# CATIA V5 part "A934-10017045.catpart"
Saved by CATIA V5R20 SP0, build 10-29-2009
Part number: A934-10017045
Source: Unknown
Property "A": "60.000"
Property "ARTICLENO": "A934-10017045"
Property "B": "20.000"
Property "BOMINFO": "A934-10017045"
Property "CODE": "A934-10017045"
Property "L": "170.000"
Property "L1": "143.370"
Property "LINA": "A934-10017045"
Property "NB": "A934-10017045"
Property "NBSYN": "$CODE."
Property "NN": "A934"
Property "NT": "VDI 3357 H-Type Cam Drivers, self-lubricating"
Property "SUPPLIER": "CF"
Property "T": "45.000"
Property "W": "100.000"
Bounding box of the stored display mesh (mm): x 0 to 170, y 0 to 45, z -100 to 0
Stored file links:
  C:\Users\Utente\Desktop\3D files A934\A934-10017045.catpart
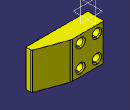
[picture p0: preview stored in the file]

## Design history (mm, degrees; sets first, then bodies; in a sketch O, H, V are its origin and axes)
Body1 "Geometry.1" (main body)
  Solid1 "A934-10017045.catpart": solid without history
